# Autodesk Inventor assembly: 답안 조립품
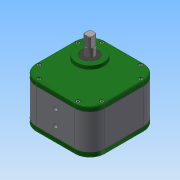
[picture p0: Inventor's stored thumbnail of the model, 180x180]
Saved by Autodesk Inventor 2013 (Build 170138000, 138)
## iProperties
Created: 2017-11
Part Number: 답안 조립품
Document SubType Name: Assembly
Designer: Administrator
Mass: 3103.25 g
Surface Area: 2353.72 cm^2
Volume: 855.505 cm^3
Density: 3.62739 g/cm^3
Author: Administrator
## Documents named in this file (11)
- C:\Users\Administrator\Desktop\371108V1026\답안 조립품.iam
- C:\Users\Administrator\Desktop\371108V1026\본체.ipt
- C:\Users\Administrator\Desktop\371108V1026\뒤커버.ipt
- C:\Users\Administrator\Desktop\371108V1026\메인축.ipt
- C:\Users\Administrator\Desktop\371108V1026\베어링 608.ipt
- C:\Users\Administrator\Desktop\371108V1026\베어링 6003.ipt
- C:\Users\Administrator\Desktop\371108V1026\볼트 M4.ipt
- C:\Users\Administrator\Desktop\371108V1026\서브축.ipt
- C:\Users\Administrator\Desktop\371108V1026\앞커버.ipt
- C:\Users\Administrator\Desktop\371108V1026\오일실 8 22 7.ipt
- C:\Users\Administrator\Desktop\371108V1026\오일실 17 32 8.ipt
